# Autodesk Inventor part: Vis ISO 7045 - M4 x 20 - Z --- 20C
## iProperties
Created: 2011-01
Part Number: Vis ISO 7045 - M4 x 20 - Z --- 20C
Document SubType Name: Modeling
Designer: eric
Density: 1 g/cm^3
Mass: 0.36171 g
Surface Area: 4.20497 cm^2
Volume: 0.36171 cm^3
Author: eric
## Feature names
1. Base1
